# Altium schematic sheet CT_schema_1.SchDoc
size 498 x 494 mm
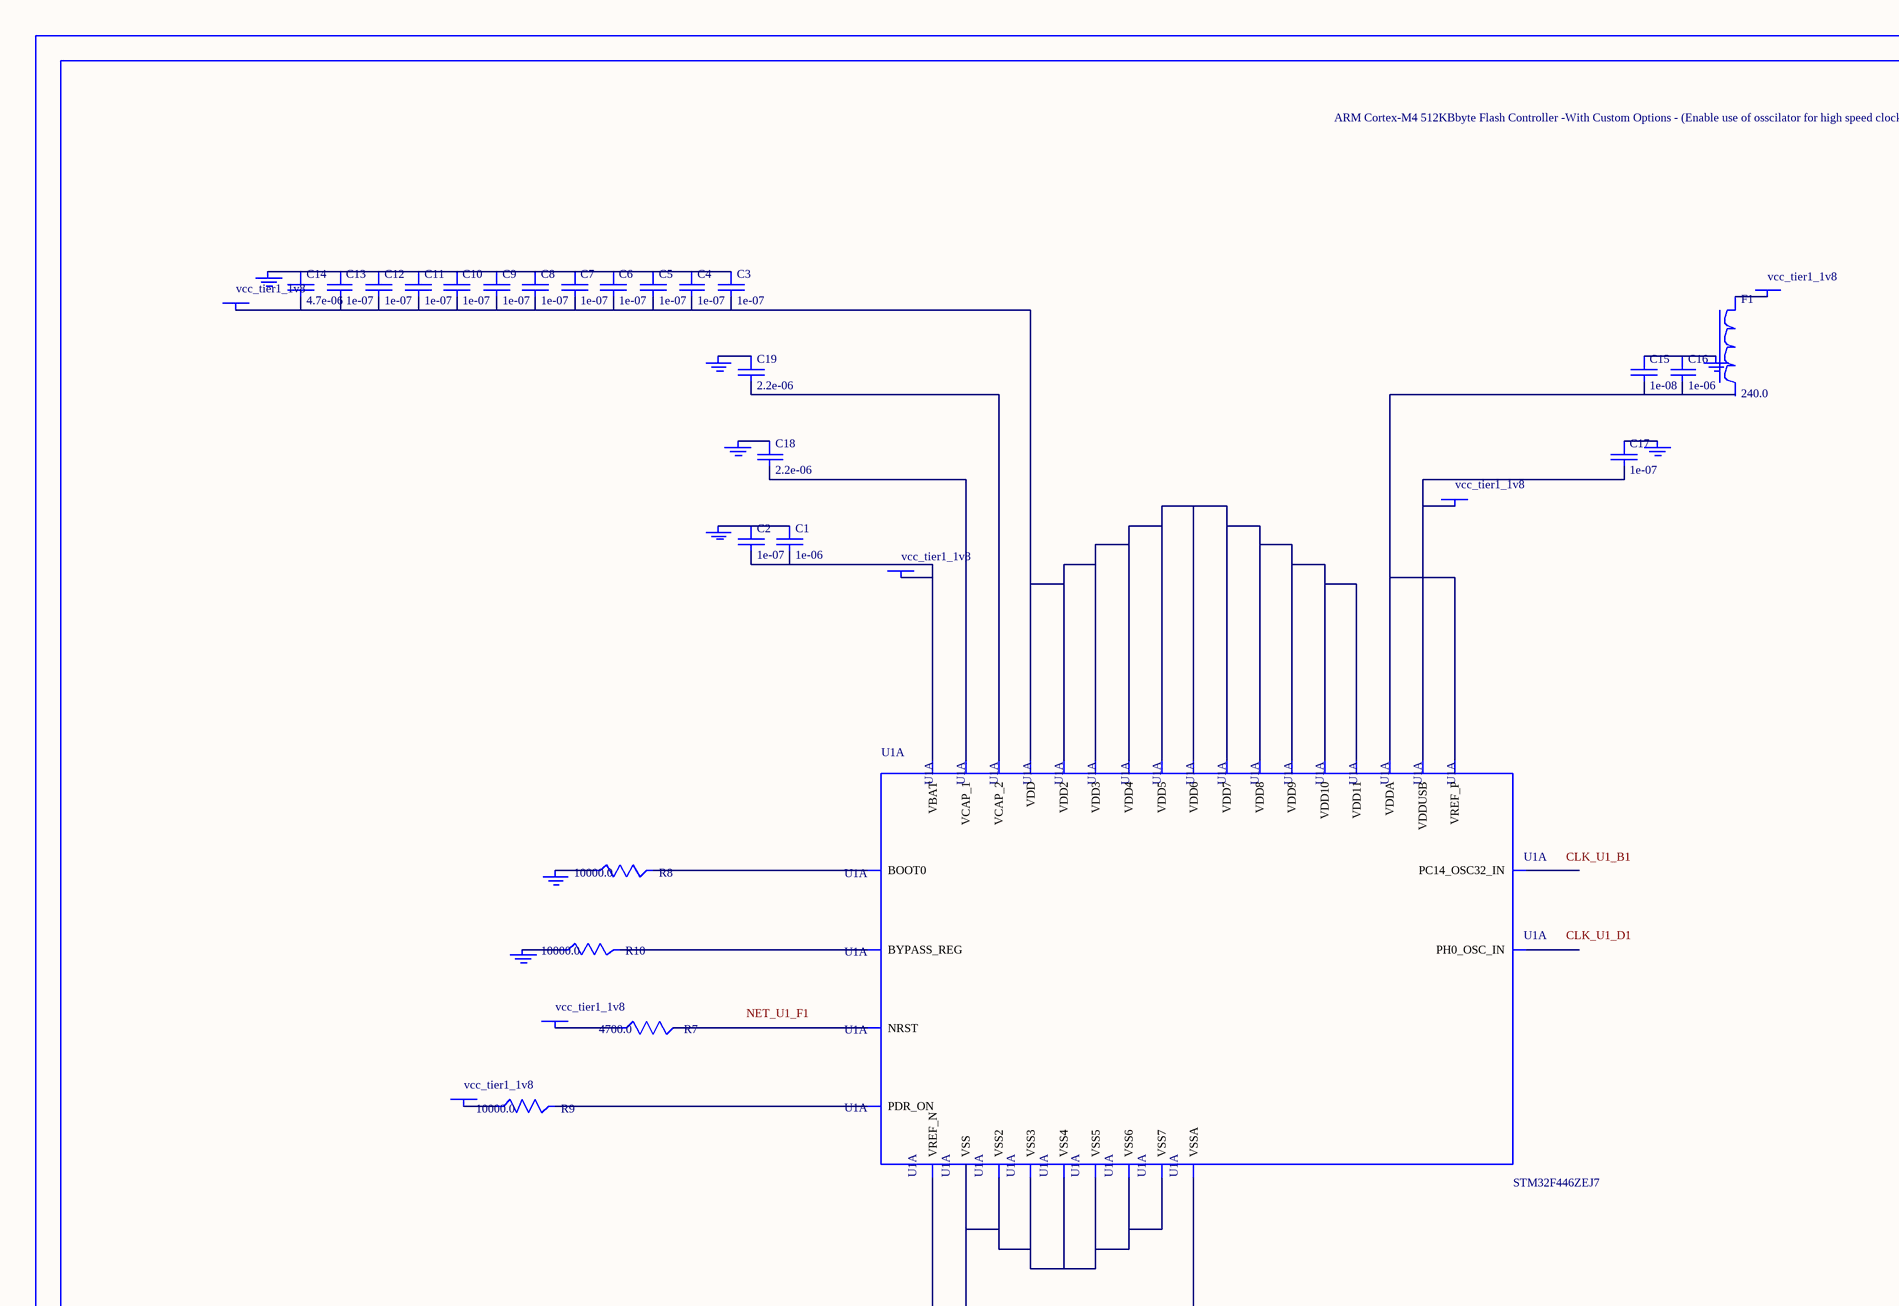
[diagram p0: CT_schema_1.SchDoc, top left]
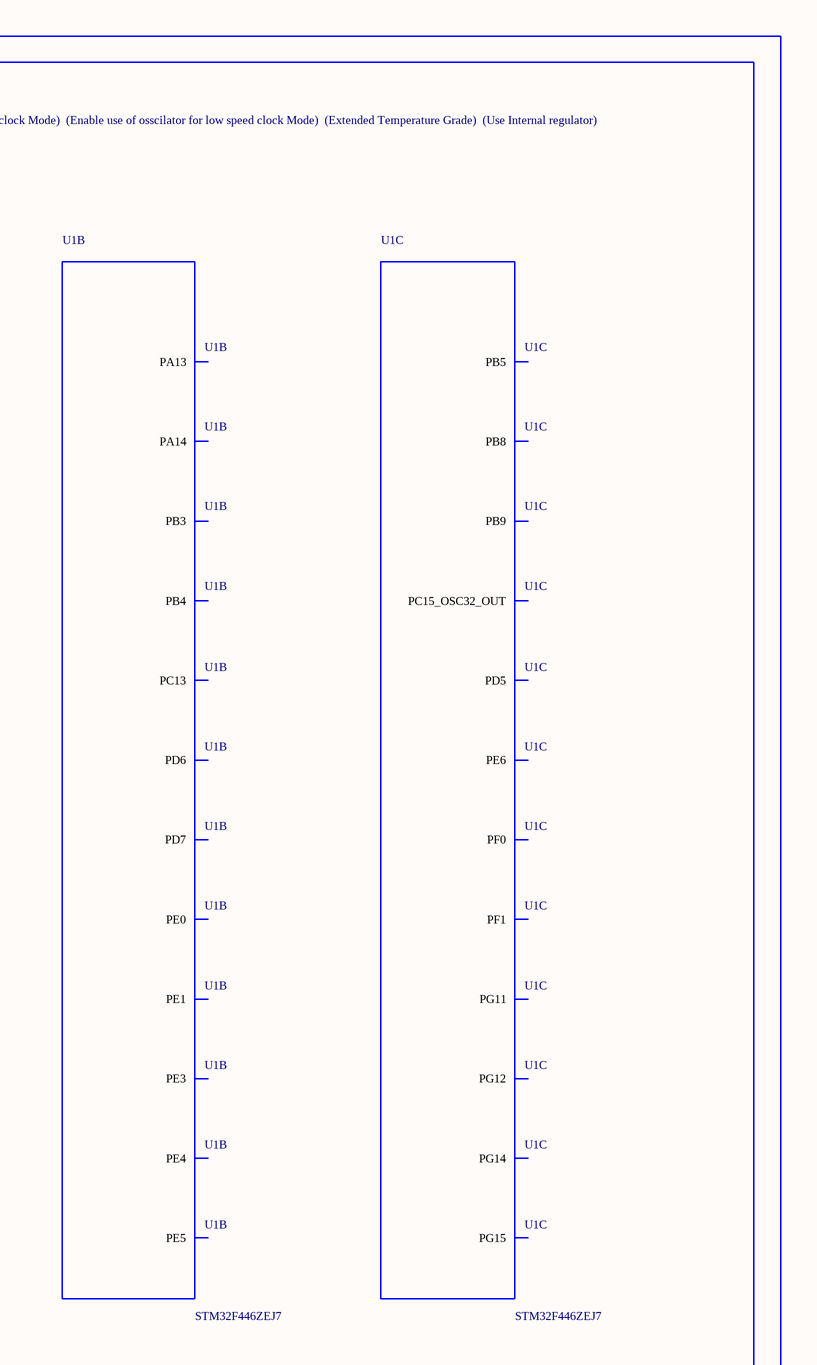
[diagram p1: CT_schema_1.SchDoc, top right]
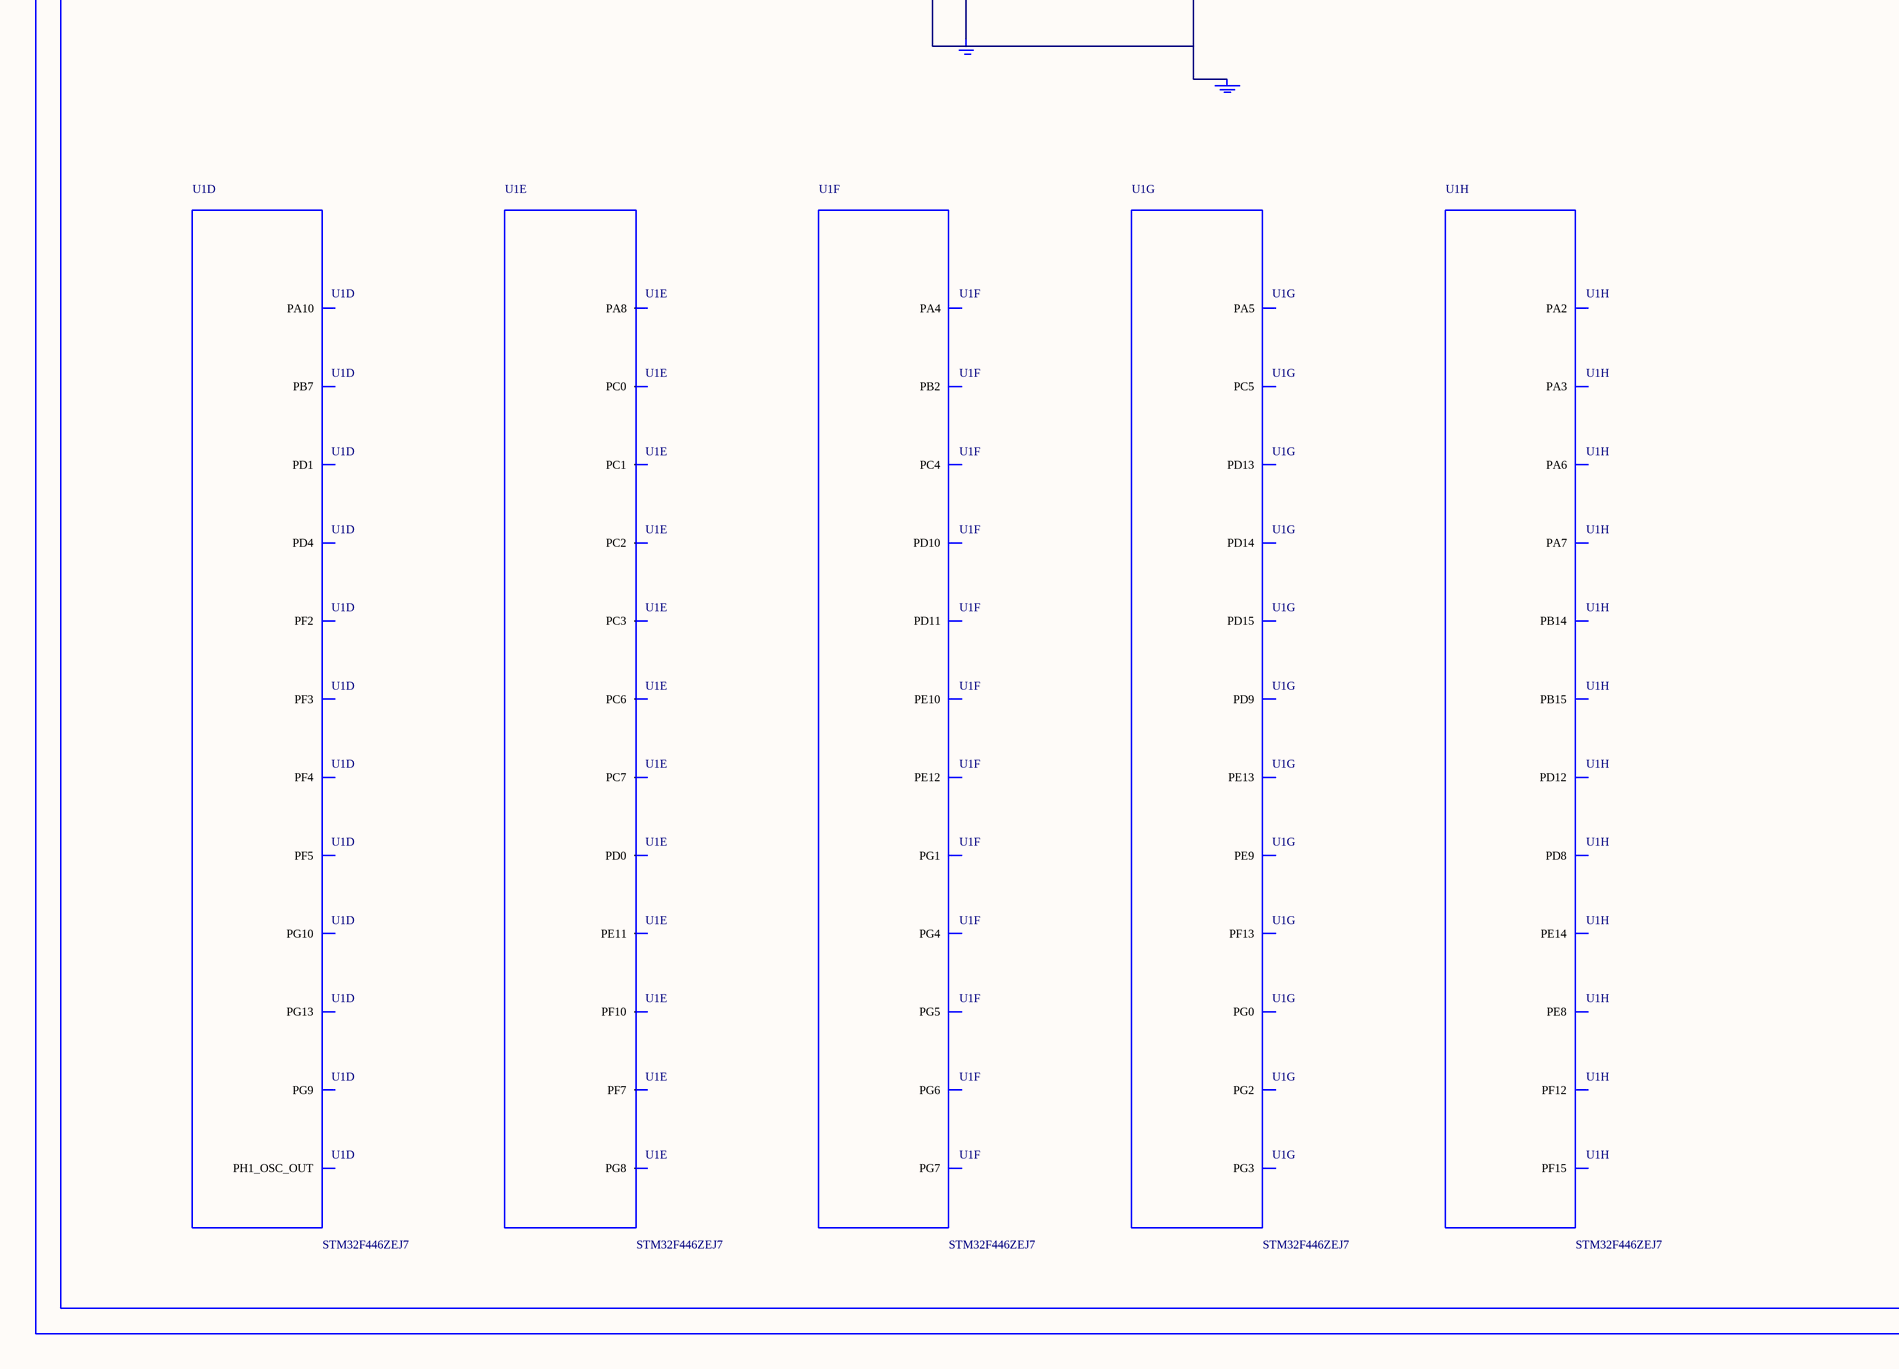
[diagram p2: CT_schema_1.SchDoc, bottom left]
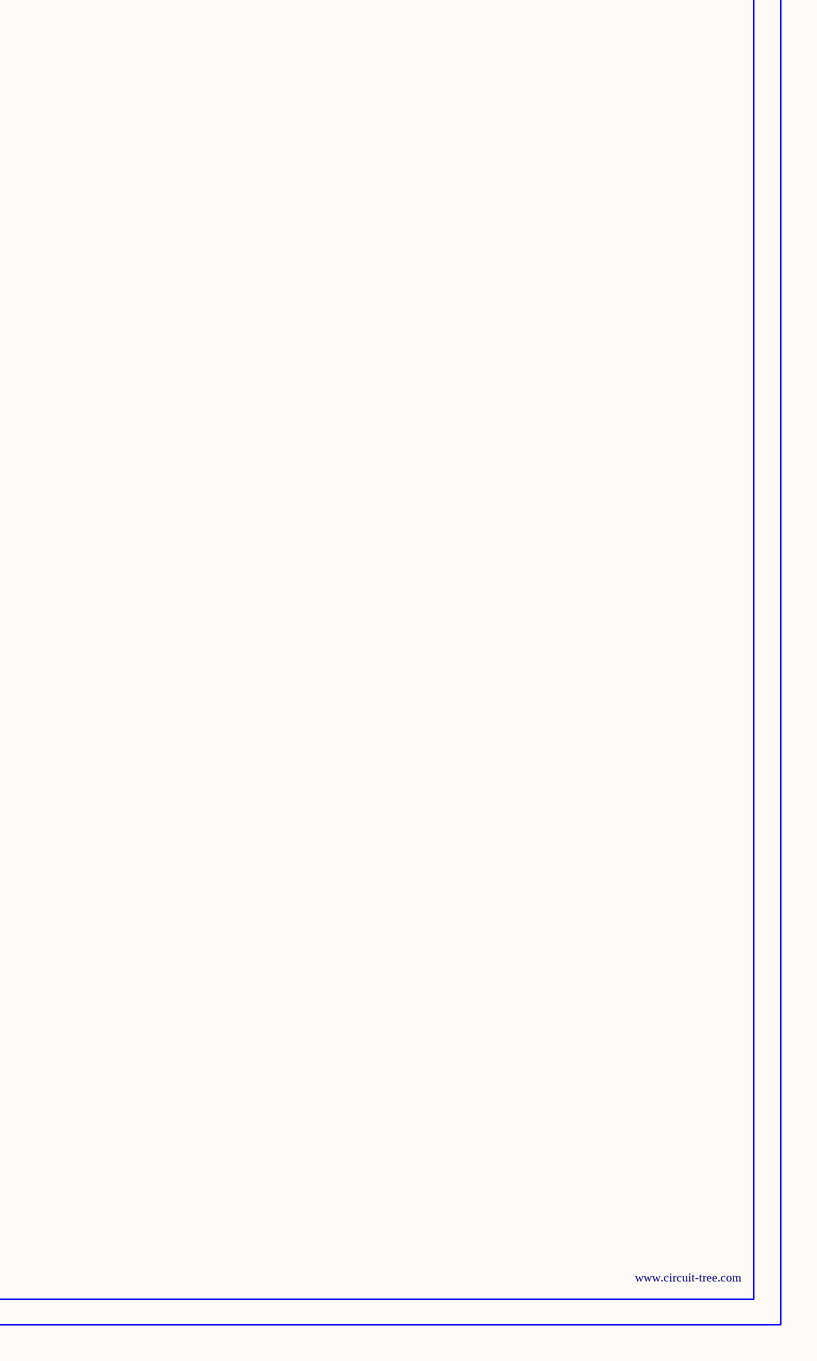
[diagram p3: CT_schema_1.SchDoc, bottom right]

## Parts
BORDER0  (no value)
C1  1e-06  [C0603]
C2  1e-07  [C0603]
C3  1e-07  [C0603]
C4  1e-07  [C0603]
C5  1e-07  [C0603]
C6  1e-07  [C0603]
C7  1e-07  [C0603]
C8  1e-07  [C0603]
C9  1e-07  [C0603]
C10  1e-07  [C0603]
C11  1e-07  [C0603]
C12  1e-07  [C0603]
C13  1e-07  [C0603]
C14  4.7e-06  [C0603]
C15  1e-08  [C0603]
C16  1e-06  [C0603]
C17  1e-07  [C0603]
C18  2.2e-06  [C0603]
C19  2.2e-06  [C0603]
F1  240.0  [L0603]
GND_INSTANCE_0_0  (no value)
GND_INSTANCE_0_1  (no value)
GND_INSTANCE_0_2  (no value)
GND_INSTANCE_0_3  (no value)
GND_INSTANCE_0_4  (no value)
GND_INSTANCE_0_5  (no value)
GND_INSTANCE_0_6  (no value)
GND_INSTANCE_0_7  (no value)
GND_INSTANCE_0_8  (no value)
GND_INSTANCE_0_9  (no value)
POWER_INSTANCE_0_0  vcc_tier1_1v8
POWER_INSTANCE_0_1  vcc_tier1_1v8
POWER_INSTANCE_0_2  vcc_tier1_1v8
POWER_INSTANCE_0_3  vcc_tier1_1v8
POWER_INSTANCE_0_4  vcc_tier1_1v8
POWER_INSTANCE_0_5  vcc_tier1_1v8
R7  4700.0  [R0603]
R8  10000.0  [R0603]
R9  10000.0  [R0603]
R10  10000.0  [R0603]
U1  STM32F446ZEJ7  [UFBGA144]  (parts A,B,C,D,E,F,G,H of 12)

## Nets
NetC1_1: C1.1 C2.1 GND_INSTANCE_0_0.0(GND)
NetC1_2: C1.2 C2.2 POWER_INSTANCE_0_0.0(PWR) U1.C2(VBAT)
NetC3_1: C3.1 C4.1 C5.1 C6.1 C7.1 C8.1 C9.1 C10.1 C11.1 C12.1 C13.1 C14.1 GND_INSTANCE_0_2.0(GND)
NetC3_2: C3.2 C4.2 C5.2 C6.2 C7.2 C8.2 C9.2 C10.2 C11.2 C12.2 C13.2 C14.2 POWER_INSTANCE_0_2.0(PWR) U1.D3(VDD) U1.F4(VDD3) U1.F5(VDD4) U1.F6(VDD5) U1.F7(VDD6) U1.F8(VDD7) U1.F9(VDD8) U1.F10(VDD2) U1.G5(VDD9) U1.G6(VDD10) U1.G7(VDD11)
NetC15_1: C15.1 C16.1 GND_INSTANCE_0_1.0(GND)
NetC15_2: C15.2 C16.2 U1.L1(VREF_P) U1.M1(VDDA)
NetC17_1: C17.1 GND_INSTANCE_0_4.0(GND)
NetC17_2: C17.2 POWER_INSTANCE_0_4.0(PWR) U1.C11(VDDUSB)
NetC18_1: C18.1 GND_INSTANCE_0_6.0(GND)
NetC18_2: C18.2 U1.H7(VCAP_1)
NetC19_1: C19.1 GND_INSTANCE_0_7.0(GND)
NetC19_2: C19.2 U1.G9(VCAP_2)
NetF1_1: F1.1 POWER_INSTANCE_0_1.0(PWR)
NetGND_INSTANCE_0_3_0: GND_INSTANCE_0_3.0(GND) R8.1
NetGND_INSTANCE_0_5_0: GND_INSTANCE_0_5.0(GND) R10.1
NetGND_INSTANCE_0_8_0: GND_INSTANCE_0_8.0(GND) U1.J1(VSSA) U1.K1(VREF_N)
NetGND_INSTANCE_0_9_0: GND_INSTANCE_0_9.0(GND) U1.D2(VSS) U1.E6(VSS2) U1.E7(VSS3) U1.G4(VSS5) U1.G8(VSS6) U1.G10(VSS4) U1.H6(VSS7)
NetPOWER_INSTANCE_0_3_0: POWER_INSTANCE_0_3.0(PWR) R9.1
NetPOWER_INSTANCE_0_5_0: POWER_INSTANCE_0_5.0(PWR) R7.1
NetR7_2: R7.2 U1.F1(NRST)
NetR8_2: R8.2 U1.D5(BOOT0)
NetR9_2: R9.2 U1.E5(PDR_ON)
NetR10_2: R10.2 U1.H5(BYPASS_REG)

Not connected (* = marked no-connect by the designer): F1 2; U1 A1(PC13) A2(PE3) A4(PE1) A5(PE0) A6(PB4) A7(PB3) A8(PD6) A9(PD7) A11(PA14) A12(PA13) B1(PC14_OSC32_IN) B2(PE4) B3(PE5) B4(PE6) B5(PB9) B6(PB5) B7(PG15) B8(PG12) B9(PD5) C1(PC15_OSC32_OUT) C3(PF0) C4(PF1) C5(PB8) C7(PG14) C8(PG11) C9(PD4) D1(PH0_OSC_IN) D4(PF2) D6(PB7) D7(PG13) D8(PG10) D10(PD1) D11(PA10) E1(PH1_OSC_OUT) E2(PF3) E3(PF4) E4(PF5) E8(PG9) E10(PD0) E12(PA8) F2(PF7) F12(PC7) G1(PF10) G11(PG8) G12(PC6) H1(PC0) H2(PC1) H3(PC2) H4(PC3) H8(PE11) H9(PD11) H10(PG7) H11(PG6) H12(PG5) J3(PA4) J4(PC4) J5(PB2) J6(PG1) J7(PE10) J8(PE12) J9(PD10) J10(PG4) J11(PG3) J12(PG2) K3(PA5) K4(PC5) K5(PF13) K6(PG0) K7(PE9) K8(PE13) K9(PD9) K10(PD13) K11(PD14) K12(PD15) L2(PA2) L3(PA6) L5(PF12) L6(PF15) L7(PE8) L8(PE14) L9(PD8) L10(PD12) L11(PB14) L12(PB15) M2(PA3) M3(PA7)

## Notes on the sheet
- Labels drawn without touching a wire or pin: CLK_U1_B1, CLK_U1_D1, NET_U1_F1

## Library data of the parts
BORDER0 = BORDER_PAGE0
C1 C16 = C0603C105K3RACTU
C2-C13 C17 = 06035C104K4Z2A
C14 = GRM188R6YA475KE15D
C15 = 06035C103K4Z2A
C18 C19 = C0603C225K8RACTU
F1 = Z0603C241ASMST
GND_INSTANCE_0_0-GND_INSTANCE_0_9 = GND
POWER_INSTANCE_0_0-POWER_INSTANCE_0_5 = PWR
R7 = RC0603JR-074K7L
R8-R10 = RC0603JR-0710KL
